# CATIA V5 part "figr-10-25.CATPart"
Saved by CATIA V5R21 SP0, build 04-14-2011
Part number: Part1
Bounding box of the stored display mesh (mm): x -65.919 to 25.581, y -200.404 to 0.194, z 0 to 71.635
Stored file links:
  D:\CATIA V5R21 E-RESOURCES\CATIA-V5R21\catia-v5r21-prt\c10-catia-v5r20-prt\c10-catia-v5r21-figr-10-25.CATPart
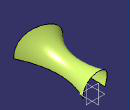
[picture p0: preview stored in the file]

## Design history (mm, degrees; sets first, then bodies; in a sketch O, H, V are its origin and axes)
Set1
  Sketch1 on xy-plane, origin (0, 0, 0), H (1, 0, 0), V (0, 1, 0)
    spline S1 through (-36.6295, 0) (-39.5961, -76.7629) (-56.6868, -154.7631) (-92.5015, -194.2587)
    point P1 (-36.6295, 0)
    coincidence: P1 H
  Sketch2 on xy-plane, origin (0, 0, 0), H (1, 0, 0), V (0, 1, 0)
    spline S1 through (25.5807, 0) (5.5021, -50.6307) (25.5807, -200.404)
    point P1 (25.5807, 0)
    coincidence: P1 H
  Sketch3 on zx-plane, origin (0, 0, 0), H (-1, 0, 0), V (0, 0, 1)
    spline S1 through (-25.5807, 0) (16.4189, 47.2175) (28.9802, 46.33) (36.6295, 0)
    reference projected point E1 (36.6295, 0) from vertex of Sketch1
    reference projected point E2 (-25.5807, 0) from vertex of Sketch2
    point P1 (-25.5807, 0)
    point P2 (36.6295, 0)
    coincidence: P1 H, P2 H, E1 P2, P1 E2
  Sweep1: type Unspec, Profile Sketch3, Guide (Sketch1; Sketch2), FittingPoints (vertex of Sketch1; vertex of Sketch2)
Body1 (main body)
